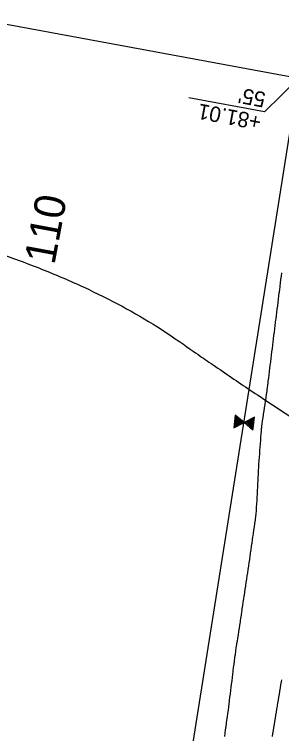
# Model space of a CAD drawing. Extents: x 674098 to 689971, y 764717 to 781049.
# Drawn here: x 688496.5 to 688600.5, y 765920.7 to 766201 of the extents above; entities that cross this region are included whole.
import ezdxf

# ---------------------------------------------------------------- set-up
doc = ezdxf.new("R2010")
doc.units = 0
for name, color, linetype in [('FLOODPLAIN', 7, 'Continuous'), ('R_Fence', 7, 'Continuous'), ('R_Horz Alg', 7, 'Continuous'), ('R_Horz Alg Station Annot', 7, 'Continuous'), ('R_Proposed Const Limits', 7, 'Continuous'), ('R_Proposed Road', 7, 'Continuous'), ('R_Proposed Shoulder S1', 7, 'Continuous'), ('R_ROW', 7, 'Continuous'), ('R_ROW Annot', 7, 'Continuous'), ('S_EXIST_ROW', 7, 'Continuous')]:
    doc.layers.add(name, color=color, linetype=linetype)

msp = doc.modelspace()

# ---------------------------------------------------------------- linework, layer by layer
at = {"layer": 'FLOODPLAIN'}
msp.add_open_spline([(687720.93, 765952.26), (687778.36, 766010.11), (687818.58, 766026.73), (687865.88, 766035.53), (687900.32, 766027.46), (687971.79, 766010.71), (687996.8, 765994.57), (688033.36, 766007.25), (688051.03, 766027.11), (688052.57, 766065.83), (688149.21, 766117.06), (688189.14, 766131.99), (688217.73, 766125.29), (688254.11, 766123.43), (688329.61, 766125.06), (688414.48, 766126.21), (688456.69, 766120.07), (688534.31, 766092.2), (688588.47, 766053.98), (688667.06, 766003.49), (688675.83, 765962.56), (688689.19, 765943.25), (688691.21, 765898.82), (688686.99, 765851.93), (688700.19, 765828.01), (688709.66, 765819.75), (688726.48, 765822.75), (688756.45, 765844.6), (688793.54, 765873.97), (688815.68, 765885.35), (688838.55, 765872.15), (688859.55, 765848.56), (688852.23, 765830.57), (688864.28, 765797.08), (688875.92, 765781.82), (688895.44, 765777.24), (688920.07, 765784), (688941.19, 765800.55), (688957.82, 765812.32), (689023.63, 765808.54), (689168.4, 765808.74), (689203.62, 765800.49), (689260.93, 765781.46), (689309.41, 765766.74), (689347.39, 765757.84), (689378.08, 765755.12), (689447.63, 765742.59), (689518.73, 765731.75), (689531.07, 765726.17), (689546.85, 765710.38)], degree=2, dxfattribs=at)
at = {"layer": 'R_Fence'}
for p, q in [((688582.45, 766044.5), (688584.93, 766041.39)), ((688583.56, 766043.91), (688585.38, 766041.63)), ((688589.91, 766043.97), (688589.93, 766043.95)), ((688582.14, 766041.69), (688583.12, 766040.46)), ((688582.22, 766042.39), (688583.57, 766040.69)), ((688582.29, 766043.09), (688584.03, 766040.93)), ((688582.37, 766043.79), (688584.48, 766041.16)), ((688585.51, 766042.27), (688585.84, 766041.86)), ((688586.29, 766042.1), (688587.47, 766040.63)), ((688586.74, 766042.33), (688589.39, 766039.03)), ((688587.2, 766042.57), (688589.47, 766039.73)), ((688587.65, 766042.8), (688589.54, 766040.43)), ((688588.1, 766043.03), (688589.62, 766041.14)), ((688588.55, 766043.27), (688589.7, 766041.84)), ((688589.01, 766043.5), (688589.78, 766042.54)), ((688589.46, 766043.74), (688589.86, 766043.24)), ((688581.98, 766040.28), (688582.21, 766039.99)), ((688582.06, 766040.98), (688582.67, 766040.22))]:
    msp.add_line(p, q, dxfattribs=at)
msp.add_lwpolyline([(688585.94, 766041.92), (688585.93, 766041.92), (688582.48, 766044.81), (688581.93, 766039.84), (688585.93, 766041.91), (688585.94, 766041.91), (688589.39, 766039.02), (688589.94, 766043.98), (688585.94, 766041.92)], dxfattribs=at)
at = {"layer": 'R_Horz Alg'}
msp.add_arc((696156.98, 764689.64), 7639.44, 169.35, 173.066667, dxfattribs=at)
msp.add_arc((696156.98, 764689.64), 7639.44, 169.35, 173.066667, dxfattribs=at)
at = {"layer": 'R_Proposed Const Limits'}
msp.add_lwpolyline([(688578.42, 765919.59), (688578.59, 765920.87), (688578.75, 765922.15), (688578.92, 765923.43), (688579.08, 765924.71), (688579.11, 765924.91), (688579.25, 765925.99), (688579.43, 765927.26), (688579.63, 765928.54), (688579.81, 765929.81), (688579.97, 765931.09), (688580.13, 765932.37), (688580.26, 765933.44), (688580.29, 765933.65), (688580.44, 765934.88), (688580.45, 765934.95), (688580.6, 765936.21), (688580.76, 765937.49), (688580.92, 765938.77), (688581.08, 765940.05), (688581.24, 765941.33), (688581.39, 765942.61), (688581.55, 765943.89), (688581.67, 765944.86), (688581.71, 765945.17), (688581.88, 765946.45), (688582.04, 765947.73), (688582.21, 765948.98), (688582.21, 765949.01), (688582.38, 765950.28), (688582.49, 765951.1), (688582.55, 765951.56), (688582.73, 765952.84), (688582.92, 765954.11), (688583.03, 765954.83), (688583.12, 765955.39), (688583.31, 765956.62), (688583.32, 765956.66), (688583.52, 765957.93), (688583.72, 765959.21), (688583.92, 765960.48), (688584.12, 765961.75), (688584.31, 765963.03), (688584.51, 765964.3), (688584.58, 765964.76), (688584.7, 765965.58), (688584.87, 765966.81), (688584.88, 765966.85), (688585.06, 765968.13), (688585.14, 765968.7), (688585.24, 765969.41), (688585.42, 765970.68), (688585.62, 765971.96), (688585.81, 765973.23), (688586, 765974.5), (688586.04, 765974.71), (688586.2, 765975.78), (688586.39, 765977.05), (688586.57, 765978.23), (688586.58, 765978.33), (688586.78, 765979.6), (688586.97, 765980.88), (688587.16, 765982.15), (688587.36, 765983.42), (688587.54, 765984.65), (688587.55, 765984.7), (688587.74, 765985.97), (688587.79, 765986.29), (688587.93, 765987.25), (688588.13, 765988.52), (688588.3, 765989.8), (688588.48, 765991.08), (688588.66, 765992.35), (688588.84, 765993.63), (688588.98, 765994.6), (688589.02, 765994.91), (688589.2, 765996.18), (688589.38, 765997.46), (688589.45, 765997.93), (688589.57, 765998.74), (688589.75, 766000.01), (688589.94, 766001.29), (688590.12, 766002.5), (688590.13, 766002.56), (688590.32, 766003.84), (688590.43, 766004.55), (688590.51, 766005.11), (688590.53, 766005.15), (688590.61, 766006.4), (688590.71, 766007.7), (688590.8, 766008.99), (688590.89, 766010.28), (688590.98, 766011.57), (688591.07, 766012.87), (688591.13, 766014.16), (688591.16, 766014.63), (688591.19, 766015.46), (688591.26, 766016.76), (688591.31, 766017.81), (688591.32, 766018.06), (688591.38, 766019.36), (688591.44, 766020.57), (688591.49, 766021.77), (688591.5, 766021.95), (688591.56, 766023.25), (688591.64, 766024.55), (688591.66, 766024.75), (688591.74, 766025.84), (688591.83, 766027.13), (688591.93, 766028.42), (688592.02, 766029.72), (688592.12, 766031.01), (688592.22, 766032.3), (688592.31, 766033.59), (688592.41, 766034.88), (688592.5, 766036.18), (688592.6, 766037.47), (688592.67, 766038.42), (688592.7, 766038.76), (688592.76, 766039.62), (688592.79, 766040.06), (688592.84, 766040.66), (688592.95, 766041.34), (688593.14, 766042.61), (688593.34, 766043.89), (688593.49, 766044.86), (688593.53, 766045.16), (688593.73, 766046.44), (688593.92, 766047.71), (688594.12, 766048.99), (688594.31, 766050.26), (688594.51, 766051.54), (688594.7, 766052.81), (688594.87, 766054.09), (688594.96, 766054.81), (688595.04, 766055.4), (688595.18, 766056.55), (688595.19, 766056.66), (688595.27, 766057.26), (688595.36, 766057.98), (688595.46, 766058.79), (688595.51, 766059.22), (688595.67, 766060.5), (688595.83, 766061.78), (688595.98, 766063.07), (688596.14, 766064.35), (688596.2, 766064.81), (688596.3, 766065.63), (688596.46, 766066.91), (688596.62, 766068.19), (688596.78, 766069.48), (688596.94, 766070.76), (688597.1, 766072.04), (688597.25, 766073.32), (688597.4, 766074.48), (688597.45, 766074.96), (688597.51, 766075.44), (688597.57, 766075.89), (688597.73, 766077.17), (688597.88, 766078.45), (688598.06, 766079.73), (688598.22, 766081.01), (688598.32, 766081.81), (688598.38, 766082.29), (688598.54, 766083.58), (688598.69, 766084.81), (688598.7, 766084.86), (688598.86, 766086.14), (688599.02, 766087.42), (688599.18, 766088.71), (688599.33, 766089.99), (688599.49, 766091.27), (688599.63, 766092.42), (688599.69, 766092.9), (688599.81, 766093.84), (688599.93, 766094.81), (688599.97, 766095.12), (688600.12, 766096.4), (688600.28, 766097.69), (688600.44, 766098.97), (688600.6, 766100.25)], dxfattribs=at)
at = {"layer": 'R_Proposed Road'}
msp.add_arc((696156.98, 764689.64), 7627.44, 169.35, 173.066667, dxfattribs=at)
at = {"layer": 'R_Proposed Shoulder S1'}
msp.add_lwpolyline([(688596.96, 765919.58), (688597.15, 765920.76), (688597.34, 765921.94), (688597.34, 765921.95), (688597.53, 765923.13), (688597.73, 765924.31), (688597.92, 765925.49), (688598.11, 765926.68), (688598.31, 765927.86), (688598.5, 765929.04), (688598.69, 765930.22), (688598.72, 765930.4), (688598.89, 765931.41), (688598.96, 765931.83), (688599.08, 765932.59), (688599.28, 765933.77), (688599.47, 765934.95), (688599.67, 765936.14), (688599.86, 765937.32), (688600.06, 765938.5), (688600.25, 765939.68), (688600.45, 765940.87), (688600.59, 765941.72)], dxfattribs=at)
at = {"layer": 'R_ROW'}
msp.add_line((688562.91, 765896.96), (688607.18, 766175.98), dxfattribs=at)
at = {"layer": 'R_ROW Annot'}
msp.add_lwpolyline([(688607.18, 766175.98), (688593.89, 766162.98), (688564.4, 766168.52)], dxfattribs=at)
at = {"layer": 'S_EXIST_ROW'}
msp.add_line((688661.62, 766165.87), (688405.98, 766213.31), dxfattribs=at)

# ---------------------------------------------------------------- texts
at = {"layer": 'R_Horz Alg Station Annot'}
msp.add_text('110', height=12, rotation=79.4666, dxfattribs=at).set_placement((688512.11, 766103.11))
at = {"layer": 'R_ROW Annot'}
for s, p in [("55'", (688594.66, 766170.52)), ('+81.01', (688593, 766161.67))]:
    msp.add_text(s, height=6, rotation=169.35, dxfattribs=at).set_placement(p)

doc.saveas('drawing.dxf')
